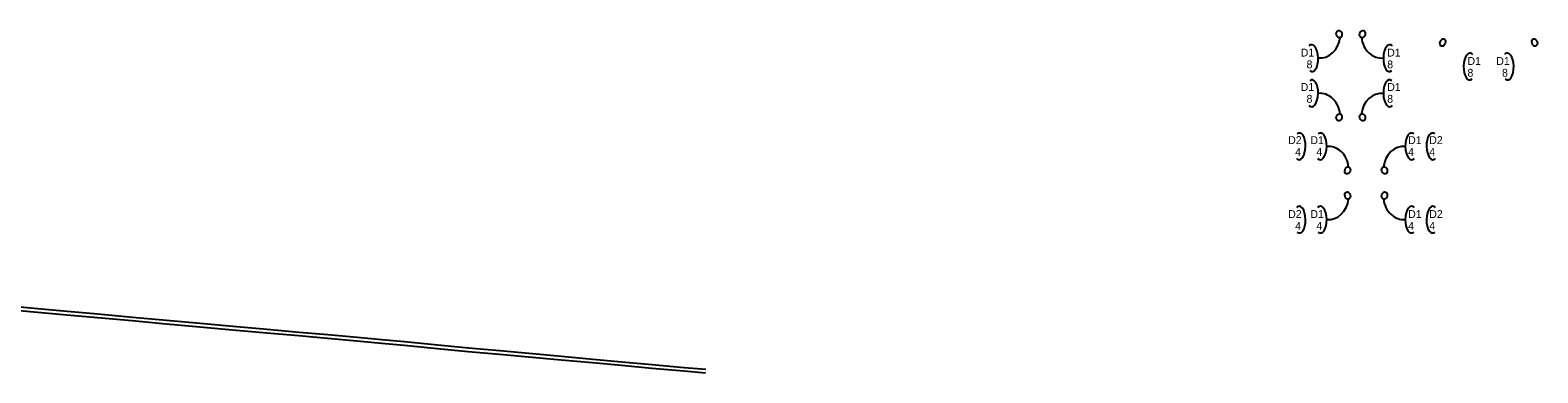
# Model space of a CAD drawing. Extents: x 1638506 to 1658005, y 834807 to 846788.
# Drawn here: x 1643213 to 1645510, y 842190 to 842713 of the extents above; entities that cross this region are included whole.
import ezdxf

# ---------------------------------------------------------------- set-up
doc = ezdxf.new("R2010")
doc.units = 0
for name, color, linetype in [('Default', 7, 'Continuous'), ('Exist Guardrail', 7, 'Continuous'), ('Old_Level_2', 7, 'Continuous')]:
    doc.layers.add(name, color=color, linetype=linetype)

msp = doc.modelspace()

# ---------------------------------------------------------------- linework, layer by layer
at = {"layer": 'Default'}
for centre, major_axis in [((1645207, 842706.8), (-1.72, 5.4)), ((1645242.6, 842706.8), (1.72, 5.4)), ((1645364.9, 842694), (1.72, 5.4)), ((1645504.9, 842694), (-1.72, 5.4)), ((1645207, 842579.9), (-1.72, -5.4)), ((1645242.6, 842579.9), (1.72, -5.4)), ((1645220, 842498.9), (-1.72, -5.4)), ((1645276.1, 842498.9), (1.72, -5.4)), ((1645220, 842460.5), (-1.72, 5.4)), ((1645276.1, 842460.5), (1.72, 5.4))]:
    msp.add_ellipse(centre, major_axis=major_axis, ratio=0.730797, dxfattribs=at)
for centre, major_axis, ratio, start_param, end_param in [((1645165.6, 842670.2), (0.5, -20.5), 0.466223, 1.570796, 3.572354), ((1645178.9, 842704.7), (3.8, 34.3), 0.862742, 3.141593, 4.712389), ((1645270.7, 842704.7), (-3.8, 34.3), 0.862742, 1.570796, 3.141593), ((1645284, 842670.2), (-0.5, -20.5), 0.466223, 2.710831, 4.712389), ((1645165.6, 842670.2), (0.5, -20.5), 0.466223, 5.884886, 7.853982), ((1645284, 842670.2), (-0.5, -20.5), 0.466223, 4.712389, 6.681485), ((1645406.3, 842657.4), (-0.5, -20.5), 0.466223, 2.710831, 4.712389), ((1645463.5, 842657.4), (0.5, -20.5), 0.466223, 1.570796, 3.572354), ((1645406.3, 842657.4), (-0.5, -20.5), 0.466223, 4.712389, 6.681485), ((1645463.5, 842657.4), (0.5, -20.5), 0.466223, 5.884886, 7.853982), ((1645165.6, 842616.5), (0.5, 20.5), 0.466223, 4.712389, 6.681485), ((1645178.9, 842582), (3.8, -34.3), 0.862742, 1.570796, 3.141593), ((1645270.7, 842582), (-3.8, -34.3), 0.862742, 3.141593, 4.712389), ((1645284, 842616.5), (-0.5, 20.5), 0.466223, 5.884886, 7.853982), ((1645165.6, 842616.5), (0.5, 20.5), 0.466223, 2.710831, 4.712389), ((1645284, 842616.5), (-0.5, 20.5), 0.466223, 1.570796, 3.572354), ((1645146.4, 842535.5), (0.5, 20.5), 0.466223, 4.712389, 6.681485), ((1645178.6, 842535.5), (0.5, 20.5), 0.466223, 4.712389, 6.681485), ((1645317.5, 842535.5), (-0.5, 20.5), 0.466223, 5.884886, 7.853982), ((1645349.7, 842535.5), (-0.5, 20.5), 0.466223, 5.884886, 7.853982), ((1645146.4, 842535.5), (0.5, 20.5), 0.466223, 2.710831, 4.712389), ((1645178.6, 842535.5), (0.5, 20.5), 0.466223, 2.710831, 4.712389), ((1645192, 842500.9), (3.8, -34.3), 0.862742, 1.570796, 3.141593), ((1645304.2, 842500.9), (-3.8, -34.3), 0.862742, 3.141593, 4.712389), ((1645317.5, 842535.5), (-0.5, 20.5), 0.466223, 1.570796, 3.572354), ((1645349.7, 842535.5), (-0.5, 20.5), 0.466223, 1.570796, 3.572354), ((1645146.4, 842423.9), (0.5, -20.5), 0.466223, 1.570796, 3.572354), ((1645178.6, 842423.9), (0.5, -20.5), 0.466223, 1.570796, 3.572354), ((1645192, 842458.5), (3.8, 34.3), 0.862742, 3.141593, 4.712389), ((1645304.2, 842458.5), (-3.8, 34.3), 0.862742, 1.570796, 3.141593), ((1645317.5, 842423.9), (-0.5, -20.5), 0.466223, 2.710831, 4.712389), ((1645349.7, 842423.9), (-0.5, -20.5), 0.466223, 2.710831, 4.712389), ((1645146.4, 842423.9), (0.5, -20.5), 0.466223, 5.884886, 7.853982), ((1645178.6, 842423.9), (0.5, -20.5), 0.466223, 5.884886, 7.853982), ((1645317.5, 842423.9), (-0.5, -20.5), 0.466223, 4.712389, 6.681485), ((1645349.7, 842423.9), (-0.5, -20.5), 0.466223, 4.712389, 6.681485)]:
    msp.add_ellipse(centre, major_axis=major_axis, ratio=ratio, start_param=start_param, end_param=end_param, dxfattribs=at)
at = {"layer": 'Exist Guardrail'}
msp.add_lwpolyline([(1643169.8, 842287.9), (1643218.4, 842283.4), (1643262.8, 842279.2), (1643315.1, 842274.5), (1643367.9, 842269.8), (1643414.5, 842265.5), (1643471, 842260.5), (1643520.8, 842255.6), (1643573.4, 842251.3), (1643622.3, 842246.9), (1643665.6, 842243.1), (1643716.2, 842238.6), (1643747.8, 842235.4), (1643782.4, 842232.3), (1643833.4, 842227.2), (1643880.3, 842222.8), (1643927.9, 842218.6), (1644021.6, 842210.1), (1644069.6, 842205.7), (1644113.7, 842201.6), (1644159.8, 842197.3), (1644208.5, 842193), (1644241.9, 842190.1)], dxfattribs=at)
at = {"layer": 'Old_Level_2'}
msp.add_lwpolyline([(1643170.3, 842293.4), (1643219, 842288.9), (1643263.3, 842284.7), (1643315.6, 842280), (1643368.4, 842275.2), (1643415, 842271), (1643471.5, 842265.9), (1643521.3, 842261.1), (1643573.9, 842256.8), (1643622.8, 842252.3), (1643666.1, 842248.5), (1643716.7, 842244.1), (1643748.3, 842240.9), (1643782.9, 842237.8), (1643834, 842232.7), (1643880.8, 842228.3), (1643928.4, 842224.1), (1644022.1, 842215.6), (1644070.1, 842211.2), (1644114.2, 842207.1), (1644160.3, 842202.8), (1644209, 842198.5), (1644242.4, 842195.5)], dxfattribs=at)

# ---------------------------------------------------------------- texts
at = {"layer": 'Default'}
for s, p in [('D1', (1645148.5, 842672.6)), ('8', (1645157.4, 842654.6)), ('8', (1645280.3, 842654.6)), ('D1', (1645280.3, 842672.6)), ('D1', (1645402.6, 842659.8)), ('D1', (1645446.5, 842659.8)), ('8', (1645402.6, 842641.8)), ('8', (1645455.3, 842641.8)), ('D1', (1645148.5, 842620.1)), ('D1', (1645280.3, 842620.1)), ('8', (1645157.4, 842602.1)), ('8', (1645280.3, 842602.1)), ('D1', (1645163.3, 842539.1)), ('D1', (1645312.2, 842539.1)), ('D2', (1645344.4, 842539.1)), ('4', (1645172.3, 842521.1)), ('4', (1645312.2, 842521.1)), ('4', (1645344.4, 842521.1)), ('D2', (1645129.4, 842426.3)), ('D1', (1645163.3, 842426.3)), ('D1', (1645312.2, 842426.3)), ('4', (1645140.1, 842408.3)), ('4', (1645172.3, 842408.3)), ('4', (1645312.2, 842408.3))]:
    msp.add_text(s, height=12, dxfattribs=at).set_placement(p)
for s, p in [('D2', (1645129.4, 842539.1)), ('4', (1645140.1, 842521.1)), ('D2', (1645344.4, 842426.3)), ('4', (1645344.4, 842408.3))]:
    msp.add_text(s, height=12, rotation=360, dxfattribs=at).set_placement(p)

doc.saveas('drawing.dxf')
